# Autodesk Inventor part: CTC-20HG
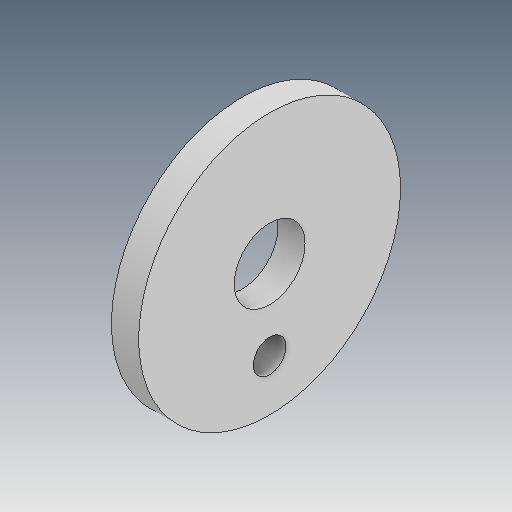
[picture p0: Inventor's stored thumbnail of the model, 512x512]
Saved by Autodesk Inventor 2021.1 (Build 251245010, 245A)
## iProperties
Created: 2018-08
Part Number: CTC-20HG
Material: Ogólny
Document SubType Name: Modeling
Designer: user
Density: 1 g/cm^3
Appearance: Domyślna
Author: user
Revision Number: ÈÎºÎ
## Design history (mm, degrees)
feature "ÊäÈë1"
node "Bryła1"
